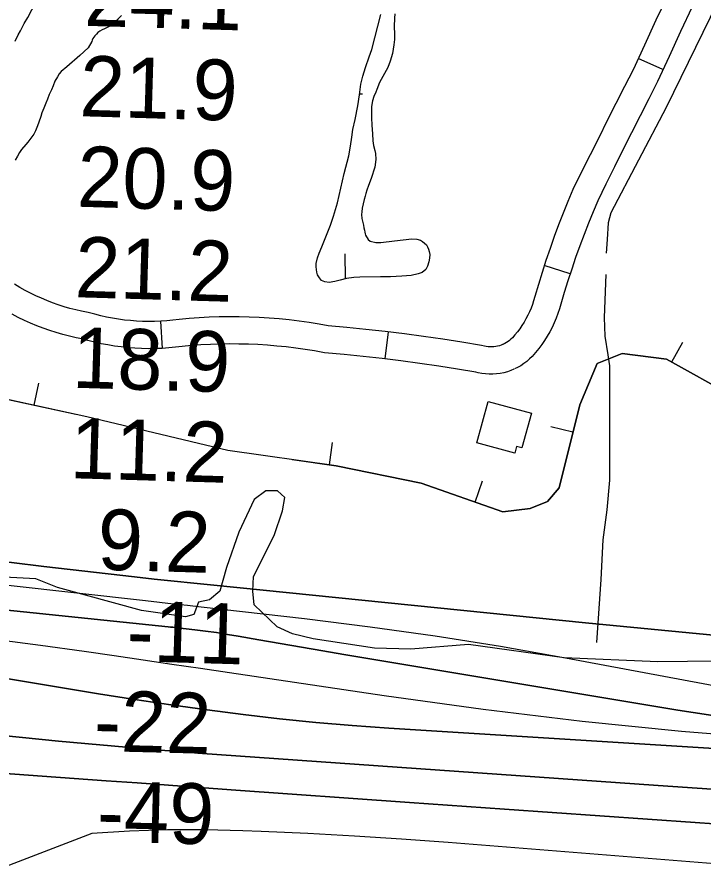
# Model space of a CAD drawing. Extents: x 3704301 to 3742427, y 506229 to 532009.
# Drawn here: x 3716465 to 3717223, y 520630 to 521564 of the extents above; entities that cross this region are included whole.
import ezdxf

# ---------------------------------------------------------------- set-up
doc = ezdxf.new("R2010")
doc.units = 0
for name, color, linetype in [('V-BLDG-OTLN', 7, 'Continuous'), ('V-BORW-LINE', 7, 'Continuous'), ('V-RIVR-EDGE', 7, 'Continuous'), ('V-RIVR-RANG', 7, 'Continuous'), ('V-ROAD-CNTR', 7, 'Continuous'), ('V-TOPO-DPTH', 7, 'Continuous'), ('V-TOPO-MAJR', 7, 'Continuous'), ('V-TOPO-MINR', 7, 'Continuous'), ('V-TOPO-SHOR', 7, 'Continuous'), ('V-TOPO-WATR', 7, 'Continuous'), ('V-WETL-SWMP', 7, 'Continuous')]:
    doc.layers.add(name, color=color, linetype=linetype)

msp = doc.modelspace()

# ---------------------------------------------------------------- linework, layer by layer
at = {"layer": 'V-BLDG-OTLN'}
msp.add_lwpolyline([(3716973.25, 521093.31), (3716985.66, 521139.12), (3717033.4, 521126.2), (3717022.99, 521087.76), (3717017.06, 521089.37), (3717015.06, 521081.99)], close=True, dxfattribs=at)
at = {"layer": 'V-BORW-LINE'}
for p, q in [((3717188.57, 521182.68), (3717200.77, 521204.5)), ((3716483.8, 521134.91), (3716489.1, 521159.35)), ((3717079.35, 521104.96), (3717055.08, 521110.98)), ((3716810.11, 521068.98), (3716813.65, 521093.73)), ((3716971.17, 521027.88), (3716979.39, 521051.49))]:
    msp.add_line(p, q, dxfattribs=at)
for points in [[(3716478.64, 521715.54), (3716425.23, 521617.24), (3716377.88, 521526.69), (3716324.19, 521406.11), (3716291.48, 521307.09), (3716294.95, 521233.04), (3716329.99, 521179.53), (3716366.16, 521160.44), (3716529.77, 521124.94)], [(3717744.34, 521658.41), (3717686.17, 521552.82), (3717619.76, 521442.96), (3717551.1, 521323.87), (3717487.5, 521251.2), (3717435.81, 521183.67), (3717360.15, 521146.31), (3717258.4, 521143.63), (3717182.9, 521185.85), (3717133.69, 521192.08), (3717106.2, 521180.95), (3717086.92, 521135.46), (3717064.15, 521043.74), (3717051.14, 521028.51), (3717032.12, 521020.85), (3717001.97, 521017.15), (3716911.44, 521048.68), (3716817.48, 521067.93), (3716698.01, 521085.02), (3716542.17, 521122.25), (3716366.16, 521160.44)], [(3716768.92, 521074.87), (3716817.48, 521067.93), (3716911.44, 521048.68), (3717001.97, 521017.15), (3717032.12, 521020.85), (3717051.14, 521028.51), (3717064.15, 521043.74), (3717086.92, 521135.46), (3717106.2, 521180.95), (3717133.69, 521192.08), (3717182.9, 521185.85), (3717258.4, 521143.63), (3717360.15, 521146.31), (3717429.68, 521180.64)]]:
    msp.add_lwpolyline(points, dxfattribs=at)
at = {"layer": 'V-RIVR-EDGE'}
msp.add_lwpolyline([(3717304.21, 520852.86), (3717173.33, 520851.38), (3717069.49, 520855.84), (3716963.87, 520870.51), (3716900.22, 520865.26), (3716860, 520866.56), (3716792.19, 520876.94), (3716769.39, 520882.39), (3716752.6, 520890.24), (3716726.85, 520914.32), (3716725.68, 520929.33), (3716726.32, 520945.54), (3716749.25, 520991.1), (3716758.32, 521018.1), (3716760.76, 521033.1), (3716752.97, 521040.32), (3716739.76, 521040.35), (3716727.13, 521030.78), (3716710.24, 520994.8), (3716696.33, 520955.82), (3716689.06, 520929.42), (3716677.63, 520919.84), (3716665.62, 520917.47), (3716660.18, 520903.68), (3716651.17, 520901.3), (3716602.56, 520908.02), (3716509.57, 520933.46), (3716485.59, 520943.13), (3716436.37, 520945.65)], dxfattribs=at)
at = {"layer": 'V-ROAD-CNTR'}
for p, q in [((3717178.89, 521505.6), (3717151.6, 521518.05)), ((3717076.27, 521279.94), (3717047.74, 521289.21)), ((3716625.79, 521197.7), (3716623.85, 521227.64)), ((3716871.83, 521186.02), (3716875.46, 521215.8))]:
    msp.add_line(p, q, dxfattribs=at)
for points in [[(3717184.11, 521587.96), (3717171.13, 521560.41), (3717158.32, 521532.79), (3717145.83, 521505.42), (3717136.41, 521486.91), (3717126.86, 521468.08), (3717117.35, 521449.23), (3717107.87, 521430.36), (3717098.42, 521411.46), (3717089, 521392.55), (3717079.43, 521373.23), (3717073.87, 521360.06), (3717068.64, 521347.15), (3717063.59, 521334.16), (3717058.72, 521321.1), (3717054.04, 521307.97), (3717049.55, 521294.78), (3717045.24, 521281.52), (3717041.12, 521268.2), (3717037.21, 521254.88), (3717035.92, 521250.37), (3717034.55, 521246.24), (3717033.02, 521242.18), (3717031.33, 521238.18), (3717029.48, 521234.25), (3717027.47, 521230.4), (3717025.3, 521226.64), (3717022.99, 521222.97), (3717020.52, 521219.39), (3717017.92, 521215.91), (3717015.18, 521212.55), (3717012.4, 521209.43), (3717010.89, 521207.92), (3717009.3, 521206.53), (3717007.61, 521205.24), (3717005.85, 521204.07), (3717004.03, 521203.02), (3717001.69, 521201.87)], [(3717211.21, 521575.09), (3717198.31, 521547.71), (3717185.57, 521520.25), (3717172.85, 521492.38), (3717163.15, 521473.32), (3717153.63, 521454.55), (3717144.14, 521435.74), (3717134.69, 521416.92), (3717125.26, 521398.07), (3717115.87, 521379.21), (3717106.71, 521360.72), (3717101.6, 521348.6), (3717096.52, 521336.08), (3717091.63, 521323.48), (3717086.91, 521310.82), (3717082.37, 521298.1), (3717078.02, 521285.3), (3717073.84, 521272.45), (3717069.85, 521259.55), (3717066.02, 521246.53), (3717064.59, 521241.53), (3717062.85, 521236.25), (3717060.89, 521231.05), (3717058.72, 521225.93), (3717056.35, 521220.9), (3717053.78, 521215.97), (3717051, 521211.15), (3717048.04, 521206.45), (3717044.88, 521201.87), (3717041.55, 521197.42), (3717038.03, 521193.11), (3717034.23, 521188.83), (3717031.36, 521185.97), (3717028.29, 521183.29), (3717025.07, 521180.82), (3717021.68, 521178.56), (3717018.15, 521176.53), (3717014.94, 521174.95)], [(3717002.58, 521202.27), (3717000.17, 521201.27), (3716998.17, 521200.59), (3716996.13, 521200.05), (3716994.06, 521199.64), (3716991.97, 521199.36), (3716989.86, 521199.22), (3716987.75, 521199.22), (3716985.64, 521199.35), (3716983.55, 521199.62), (3716981.48, 521200.03), (3716978.28, 521200.88), (3716956.57, 521204.5), (3716935.44, 521207.78), (3716914.28, 521210.83), (3716893.09, 521213.65), (3716871.87, 521216.24), (3716850.62, 521218.6), (3716829.34, 521220.72), (3716808.81, 521222.54), (3716798.73, 521224.38), (3716787.79, 521226.15), (3716776.81, 521227.71), (3716765.81, 521229.04), (3716754.79, 521230.17), (3716743.74, 521231.08), (3716732.68, 521231.78), (3716721.61, 521232.26), (3716710.53, 521232.52), (3716699.44, 521232.56), (3716688.36, 521232.39), (3716677.28, 521232.01), (3716666.22, 521231.4), (3716655.17, 521230.58), (3716644.07, 521229.54), (3716637.02, 521228.68), (3716630.37, 521228.06), (3716623.7, 521227.63), (3716617.02, 521227.38), (3716610.33, 521227.33), (3716603.65, 521227.46), (3716596.98, 521227.78), (3716590.31, 521228.3), (3716583.67, 521229), (3716577.04, 521229.89), (3716570.45, 521230.96), (3716563.88, 521232.22), (3716557.36, 521233.67), (3716550.88, 521235.3), (3716543.66, 521237.34), (3716536.29, 521238.78), (3716529.77, 521240.25), (3716523.31, 521241.91), (3716516.89, 521243.76), (3716510.52, 521245.79), (3716504.22, 521248.01), (3716497.99, 521250.4), (3716491.82, 521252.98), (3716485.74, 521255.73), (3716479.73, 521258.66), (3716473.82, 521261.76), (3716467.99, 521265.03), (3716462.26, 521268.46)], [(3717014.04, 521174.55), (3717010.74, 521173.18), (3717006.89, 521171.87), (3717002.95, 521170.82), (3716998.96, 521170.02), (3716994.93, 521169.49), (3716990.87, 521169.22), (3716986.8, 521169.22), (3716982.74, 521169.48), (3716978.71, 521170), (3716974.71, 521170.79), (3716971.94, 521171.53), (3716951.8, 521174.88), (3716931, 521178.11), (3716910.16, 521181.12), (3716889.3, 521183.89), (3716868.4, 521186.44), (3716847.48, 521188.76), (3716826.53, 521190.85), (3716804.8, 521192.78), (3716793.65, 521194.81), (3716783.29, 521196.49), (3716772.89, 521197.96), (3716762.47, 521199.23), (3716752.03, 521200.3), (3716741.57, 521201.16), (3716731.09, 521201.82), (3716720.6, 521202.27), (3716710.11, 521202.52), (3716699.61, 521202.56), (3716689.12, 521202.4), (3716678.63, 521202.04), (3716668.15, 521201.46), (3716657.67, 521200.69), (3716647.29, 521199.71), (3716640.23, 521198.85), (3716632.73, 521198.15), (3716625.22, 521197.66), (3716617.69, 521197.39), (3716610.16, 521197.33), (3716602.63, 521197.48), (3716595.1, 521197.84), (3716587.59, 521198.42), (3716580.1, 521199.21), (3716572.63, 521200.21), (3716565.2, 521201.42), (3716557.8, 521202.84), (3716550.45, 521204.47), (3716543.15, 521206.31), (3716536.69, 521208.13), (3716530.1, 521209.42), (3716522.74, 521211.09), (3716515.43, 521212.96), (3716508.18, 521215.05), (3716500.99, 521217.34), (3716493.87, 521219.85), (3716486.82, 521222.55), (3716479.86, 521225.46), (3716472.98, 521228.57), (3716466.2, 521231.88), (3716459.51, 521235.38)]]:
    msp.add_lwpolyline(points, dxfattribs=at)
at = {"layer": 'V-TOPO-DPTH'}
for points in [[(3716422.82, 520965.58), (3716494.63, 520956.65), (3716594.78, 520945.3), (3716616.65, 520942.87), (3716638.51, 520940.49), (3716660.39, 520938.19), (3716682.27, 520935.95), (3717093.28, 520894.67), (3717165.91, 520887.45), (3717238.55, 520880.35), (3717311.21, 520873.4), (3717383.87, 520866.56), (3717504.36, 520855.36), (3717516.8, 520854.49), (3717529.24, 520853.99), (3717541.68, 520854.06), (3717554.14, 520854.5), (3717613.93, 520857.99), (3717656.21, 520861.1), (3717698.4, 520865.07)], [(3716069.97, 520948.17), (3716631.88, 520890.16), (3716634.5, 520889.88), (3716637.11, 520889.6), (3716639.73, 520889.31), (3716642.34, 520889.01), (3716661.27, 520886.82), (3716673.33, 520885.31), (3716685.37, 520883.66), (3716697.37, 520881.79), (3716709.36, 520879.78), (3716732.35, 520875.71), (3716755.82, 520871.59), (3716779.3, 520867.52), (3716802.79, 520863.52), (3716826.29, 520859.57), (3717195.39, 520798.04), (3717250.79, 520789.57)], [(3717250.79, 520789.57), (3717195.39, 520798.04), (3716826.29, 520859.57), (3716802.79, 520863.52), (3716779.3, 520867.52), (3716755.82, 520871.59), (3716732.35, 520875.71), (3716709.36, 520879.78), (3716697.37, 520881.79), (3716685.37, 520883.66), (3716673.33, 520885.31), (3716661.27, 520886.82), (3716642.34, 520889.01), (3716639.73, 520889.31), (3716637.11, 520889.6), (3716634.5, 520889.88), (3716631.88, 520890.16), (3716069.97, 520948.17)], [(3717865.55, 520735.46), (3717570.64, 520736.94), (3717550.21, 520737.22), (3717529.79, 520737.73), (3717509.39, 520738.6), (3717488.99, 520739.7), (3716875.78, 520778.19), (3716835.49, 520781.09), (3716795.25, 520784.47), (3716755.07, 520788.58), (3716714.95, 520793.17), (3716674.89, 520798.37), (3716634.87, 520803.89), (3716594.93, 520809.88), (3716555.03, 520816.2), (3716435.17, 520835.9)], [(3716435.17, 520835.9), (3716555.03, 520816.2), (3716594.93, 520809.88), (3716634.87, 520803.89), (3716674.89, 520798.37), (3716714.95, 520793.17), (3716755.07, 520788.58), (3716795.25, 520784.47), (3716835.49, 520781.09), (3716875.78, 520778.19), (3717488.99, 520739.7), (3717509.39, 520738.6), (3717529.79, 520737.73), (3717550.21, 520737.22), (3717570.64, 520736.94), (3717865.55, 520735.46)], [(3717700.67, 520693.03), (3717612.97, 520694.05), (3717571.48, 520694.75), (3717529.99, 520695.75), (3717488.52, 520697.19), (3717447.06, 520698.93), (3717411.09, 520700.63), (3717351.66, 520703.65), (3717292.24, 520706.95), (3717232.85, 520710.67), (3717173.48, 520714.66), (3716664.83, 520750.67), (3716649.11, 520751.83), (3716633.4, 520753.04), (3716617.7, 520754.34), (3716602, 520755.7), (3716510.55, 520763.89), (3716449.22, 520770.04)], [(3716449.22, 520770.04), (3716510.55, 520763.89), (3716602, 520755.7), (3716617.7, 520754.34), (3716633.4, 520753.04), (3716649.11, 520751.83), (3716664.83, 520750.67), (3717173.48, 520714.66), (3717232.85, 520710.67), (3717292.24, 520706.95), (3717351.66, 520703.65), (3717411.09, 520700.63), (3717447.06, 520698.93), (3717488.52, 520697.19), (3717529.99, 520695.75), (3717571.48, 520694.75), (3717612.97, 520694.05), (3717700.67, 520693.03)], [(3717857.11, 520640.66), (3717555.85, 520651.4), (3717543.02, 520651.92), (3717530.18, 520652.52), (3717517.36, 520653.25), (3717504.54, 520654.06), (3717319.65, 520666.67), (3717214.39, 520673.9), (3717109.14, 520681.2), (3717003.89, 520688.61), (3716898.65, 520696.08), (3716701.47, 520710.19), (3716666.91, 520712.67), (3716632.36, 520715.15), (3716597.81, 520717.64), (3716563.25, 520720.13), (3716128.46, 520751.55)], [(3716128.46, 520751.55), (3716563.25, 520720.13), (3716597.81, 520717.64), (3716632.36, 520715.15), (3716666.91, 520712.67), (3716701.47, 520710.19), (3716898.65, 520696.08), (3717003.89, 520688.61), (3717109.14, 520681.2), (3717214.39, 520673.9), (3717319.65, 520666.67), (3717504.54, 520654.06), (3717517.36, 520653.25), (3717530.18, 520652.52), (3717543.02, 520651.92), (3717555.85, 520651.4), (3717857.11, 520640.66)]]:
    msp.add_lwpolyline(points, dxfattribs=at)
at = {"layer": 'V-TOPO-MAJR'}
msp.add_lwpolyline([(3717729.2, 520592.62), (3717662.93, 520596.4), (3717603.63, 520600.09), (3717567.02, 520602.46), (3717530.43, 520604.97), (3717493.84, 520607.66), (3717457.27, 520610.49), (3716941.38, 520651.73), (3716889.72, 520655.54), (3716838.05, 520658.93), (3716786.33, 520661.69), (3716734.59, 520664.03), (3716714.64, 520664.81), (3716672.87, 520665.73), (3716631.11, 520665.71), (3716589.38, 520664.29), (3716547.67, 520661.92), (3715740.63, 520351.74)], dxfattribs=at)
at = {"layer": 'V-TOPO-MINR'}
for points in [[(3717250.79, 520789.57), (3717195.39, 520798.04), (3716826.29, 520859.57), (3716802.79, 520863.52), (3716779.3, 520867.52), (3716755.82, 520871.59), (3716732.35, 520875.71), (3716709.36, 520879.78), (3716697.37, 520881.79), (3716685.37, 520883.66), (3716673.33, 520885.31), (3716661.27, 520886.82), (3716642.34, 520889.01), (3716639.73, 520889.31), (3716637.11, 520889.6), (3716634.5, 520889.88), (3716631.88, 520890.16), (3716069.97, 520948.17)], [(3717375.64, 520798.95), (3717070.99, 520855.62), (3716999.19, 520868.19), (3716927.23, 520879.75), (3716855.05, 520889.79), (3716782.71, 520898.81), (3716668.6, 520911.82), (3716653.21, 520913.57), (3716637.81, 520915.31), (3716622.42, 520917.04), (3716607.02, 520918.75), (3716378.93, 520944.12)], [(3717686.78, 520749.96), (3717557.81, 520749.93), (3717543.76, 520750.07), (3717529.73, 520750.42), (3717515.71, 520751.06), (3717501.69, 520751.9), (3717309.45, 520765.54), (3717199.46, 520774.62), (3717089.65, 520785.39), (3716980.12, 520798.7), (3716870.78, 520813.71), (3716699.63, 520839.23), (3716667.81, 520843.95), (3716635.99, 520848.65), (3716604.16, 520853.31), (3716572.33, 520857.95), (3716539.26, 520862.75), (3716490.86, 520869.48), (3716442.41, 520875.84)], [(3717865.55, 520735.46), (3717570.64, 520736.94), (3717550.21, 520737.22), (3717529.79, 520737.73), (3717509.39, 520738.6), (3717488.99, 520739.7), (3716875.78, 520778.19), (3716835.49, 520781.09), (3716795.25, 520784.47), (3716755.07, 520788.58), (3716714.95, 520793.17), (3716674.89, 520798.37), (3716634.87, 520803.89), (3716594.93, 520809.88), (3716555.03, 520816.2), (3716435.17, 520835.9)], [(3717700.67, 520693.03), (3717612.97, 520694.05), (3717571.48, 520694.75), (3717529.99, 520695.75), (3717488.52, 520697.19), (3717447.06, 520698.93), (3717411.09, 520700.63), (3717351.66, 520703.65), (3717292.24, 520706.95), (3717232.85, 520710.67), (3717173.48, 520714.66), (3716664.83, 520750.67), (3716649.11, 520751.83), (3716633.4, 520753.04), (3716617.7, 520754.34), (3716602, 520755.7), (3716510.55, 520763.89), (3716449.22, 520770.04)], [(3717857.11, 520640.66), (3717555.85, 520651.4), (3717543.02, 520651.92), (3717530.18, 520652.52), (3717517.36, 520653.25), (3717504.54, 520654.06), (3717319.65, 520666.67), (3717214.39, 520673.9), (3717109.14, 520681.2), (3717003.89, 520688.61), (3716898.65, 520696.08), (3716701.47, 520710.19), (3716666.91, 520712.67), (3716632.36, 520715.15), (3716597.81, 520717.64), (3716563.25, 520720.13), (3716128.46, 520751.55)]]:
    msp.add_lwpolyline(points, dxfattribs=at)
at = {"layer": 'V-TOPO-SHOR'}
for points in [[(3717375.59, 521860.13), (3717287.58, 521678.8), (3717182.6, 521463.82), (3717121.44, 521347.33), (3717118.31, 521336.26), (3717117.13, 521318.1), (3717115.98, 521302.97)], [(3716462.97, 521537.01), (3716466.29, 521543.88), (3716468.56, 521548.33), (3716472.7, 521556.41), (3716476.83, 521563.28), (3716481.37, 521571.56), (3716485.29, 521578.22), (3716488.39, 521583.07), (3716492.1, 521589.12), (3716496.01, 521594.77), (3716500.13, 521600.82), (3716504.86, 521607.08), (3716509.37, 521612.31), (3716513.69, 521617.96), (3716514.92, 521619.36), (3716516.77, 521621.17), (3716519.23, 521624.4), (3716523.39, 521633.91), (3716525.26, 521639.17), (3716534, 521661.02), (3716555.58, 521709.14), (3716561.37, 521720.66), (3716563.05, 521726.33)], [(3716580.54, 521565.41), (3716578.7, 521563.73), (3716576.38, 521561.26), (3716574.06, 521558.78), (3716571.06, 521556.03), (3716567.65, 521553.63), (3716564.66, 521552.04), (3716561.74, 521550.71), (3716558.96, 521549.45), (3716556.58, 521547.99), (3716554.33, 521546.45), (3716552.56, 521544.85), (3716550.71, 521542.91), (3716549.62, 521541.43), (3716548.66, 521539.81), (3716547.96, 521538.13), (3716547.48, 521536.51), (3716543.52, 521529.75)], [(3716543.52, 521529.75), (3716534.3, 521521.1), (3716519.76, 521508.86), (3716513.62, 521503.63), (3716511.36, 521500.81), (3716509.51, 521497.78), (3716506.82, 521492.73), (3716504.74, 521487.68), (3716502.87, 521483.23), (3716500.59, 521478.17), (3716498.51, 521473.11), (3716496.84, 521468.46), (3716494.56, 521463.2), (3716492.48, 521457.74), (3716491.02, 521453.69), (3716489.13, 521447.42), (3716487.47, 521443.37), (3716485.39, 521438.11), (3716483.32, 521434.27), (3716480.23, 521430.04), (3716476.94, 521425.6), (3716474.48, 521422.78), (3716469.75, 521417.34), (3716467.49, 521414.12), (3716465.42, 521410.08), (3716462.74, 521405.43)], [(3717115.75, 521279.26), (3717113.79, 521231.84), (3717114.6, 521211.15), (3717117.94, 521190.43), (3717119.84, 521178.29), (3717119.65, 521052.14), (3717116.82, 521019.37), (3717112.47, 520986.11), (3717110.03, 520942.23), (3717105.38, 520872.71)]]:
    msp.add_lwpolyline(points, dxfattribs=at)
at = {"layer": 'V-TOPO-WATR'}
msp.add_lwpolyline([(3717698.4, 520865.07), (3717656.21, 520861.1), (3717613.93, 520857.99), (3717554.14, 520854.5), (3717541.68, 520854.06), (3717529.24, 520853.99), (3717516.8, 520854.49), (3717504.36, 520855.36), (3717383.87, 520866.56), (3717311.21, 520873.4), (3717238.55, 520880.35), (3717165.91, 520887.45), (3717093.28, 520894.67), (3716682.27, 520935.95), (3716660.39, 520938.19), (3716638.51, 520940.49), (3716616.65, 520942.87), (3716594.78, 520945.3), (3716494.63, 520956.65), (3716422.82, 520965.58)], dxfattribs=at)
at = {"layer": 'V-WETL-SWMP'}
for p, q in [((3716843.7, 521478.86), (3716846.59, 521478.89)), ((3716827.83, 521274.61), (3716827.51, 521302.13))]:
    msp.add_line(p, q, dxfattribs=at)
for points in [[(3716847.7, 521333.66), (3716848.37, 521330.92), (3716848.89, 521328.35), (3716849.26, 521326.16), (3716849.64, 521324.36), (3716850.09, 521322.8), (3716852.93, 521317.78), (3716855.17, 521316.28), (3716861.63, 521314.74), (3716867.08, 521314.77), (3716882.3, 521316.65), (3716901.42, 521318.73), (3716906.87, 521318.29), (3716910.83, 521317.08), (3716913.16, 521315.89), (3716915.32, 521314), (3716917.33, 521311.95), (3716918.64, 521309.91), (3716919.86, 521307.41), (3716920.61, 521304.75), (3716921.13, 521301.47), (3716920.78, 521297.19), (3716920.12, 521293.37), (3716918.67, 521288.55), (3716916.76, 521284.91), (3716912.68, 521281.6), (3716908.45, 521279.92), (3716900.41, 521278.36), (3716890.19, 521277.29), (3716877.64, 521276.79), (3716866.49, 521276.58), (3716843.65, 521276.33), (3716837.02, 521276.16), (3716828.98, 521274.91), (3716822.02, 521273.03), (3716816.09, 521271.45), (3716809.84, 521270.49), (3716805.17, 521271.16), (3716801.52, 521272.75), (3716799.06, 521275.66), (3716797.14, 521278.79), (3716796.46, 521281.84), (3716795.59, 521287.93), (3716795.54, 521291.36), (3716796.93, 521297.58), (3716798.69, 521302.79), (3716801.64, 521309.7), (3716811.38, 521333.85), (3716814.67, 521343.87), (3716819.09, 521358.32), (3716826.5, 521390.99), (3716831.51, 521410.27), (3716833.48, 521420.93), (3716834.9, 521431.13), (3716836.23, 521439.3), (3716838.67, 521450.42), (3716841.78, 521465.52), (3716843.53, 521477.89), (3716844.89, 521489.42), (3716847.23, 521498.51), (3716850.05, 521507.92), (3716854.14, 521519.73), (3716857.25, 521527.73), (3716867.13, 521566.53)], [(3716882.57, 521567.08), (3716882.21, 521562.33), (3716881.82, 521553.37), (3716882.05, 521544.64), (3716882.15, 521538.95), (3716881.47, 521533.03), (3716879.74, 521523.3), (3716877.16, 521514.83), (3716874.92, 521507.99), (3716865.72, 521491.4), (3716862.6, 521483.71), (3716861.33, 521480.69), (3716859.18, 521475.87), (3716857.73, 521471.21), (3716856.58, 521464.75), (3716856.53, 521459.14), (3716856.62, 521452.44), (3716857.24, 521444.25), (3716857.7, 521434.5), (3716858.33, 521427.09), (3716859.06, 521421.78), (3716860.56, 521416.31), (3716861.23, 521412.95), (3716861.32, 521406.17), (3716860.47, 521397.84), (3716856.37, 521385.33), (3716853.49, 521377.64), (3716851.65, 521372.59), (3716850.45, 521368.94), (3716849.56, 521365.99), (3716848.44, 521362.1), (3716846.24, 521352.53), (3716845.89, 521348.48), (3716845.71, 521345.45), (3716846.13, 521341.15), (3716847.7, 521333.66)]]:
    msp.add_lwpolyline(points, dxfattribs=at)

# ---------------------------------------------------------------- texts
at = {"layer": 'V-RIVR-RANG'}
for s, rotation, p in [('24.1', 358.29833, (3716538.8, 521554.07)), ('21.9', 358.29833, (3716533.44, 521454.19)), ('20.9', 358.29833, (3716530.71, 521354.22)), ('21.2', 358.29833, (3716528.24, 521254.25)), ('18.9', 358.29833, (3716525.25, 521154.3)), ('11.2', 358.29833, (3716522.79, 521054.33)), ('9.2', 358.29833, (3716553.28, 520953.38)), ('-11', 358.29833, (3716585.36, 520852.38)), ('-22', 358.57811, (3716549.29, 520753)), ('-49', 358.57811, (3716552.63, 520652.88))]:
    msp.add_text(s, height=67, rotation=rotation, dxfattribs=at).set_placement(p)

doc.saveas('drawing.dxf')
